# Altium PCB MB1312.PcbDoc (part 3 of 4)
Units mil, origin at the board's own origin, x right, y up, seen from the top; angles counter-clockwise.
Board outline 2755.91 x 5249.6 mil, 6 copper layers (Top Layer, GND, Signal, PWR, GND (Mid2), Bottom Layer), stack 74.545 mil thick; 297 components, 280 nets, 1142 pads, 623 vias.
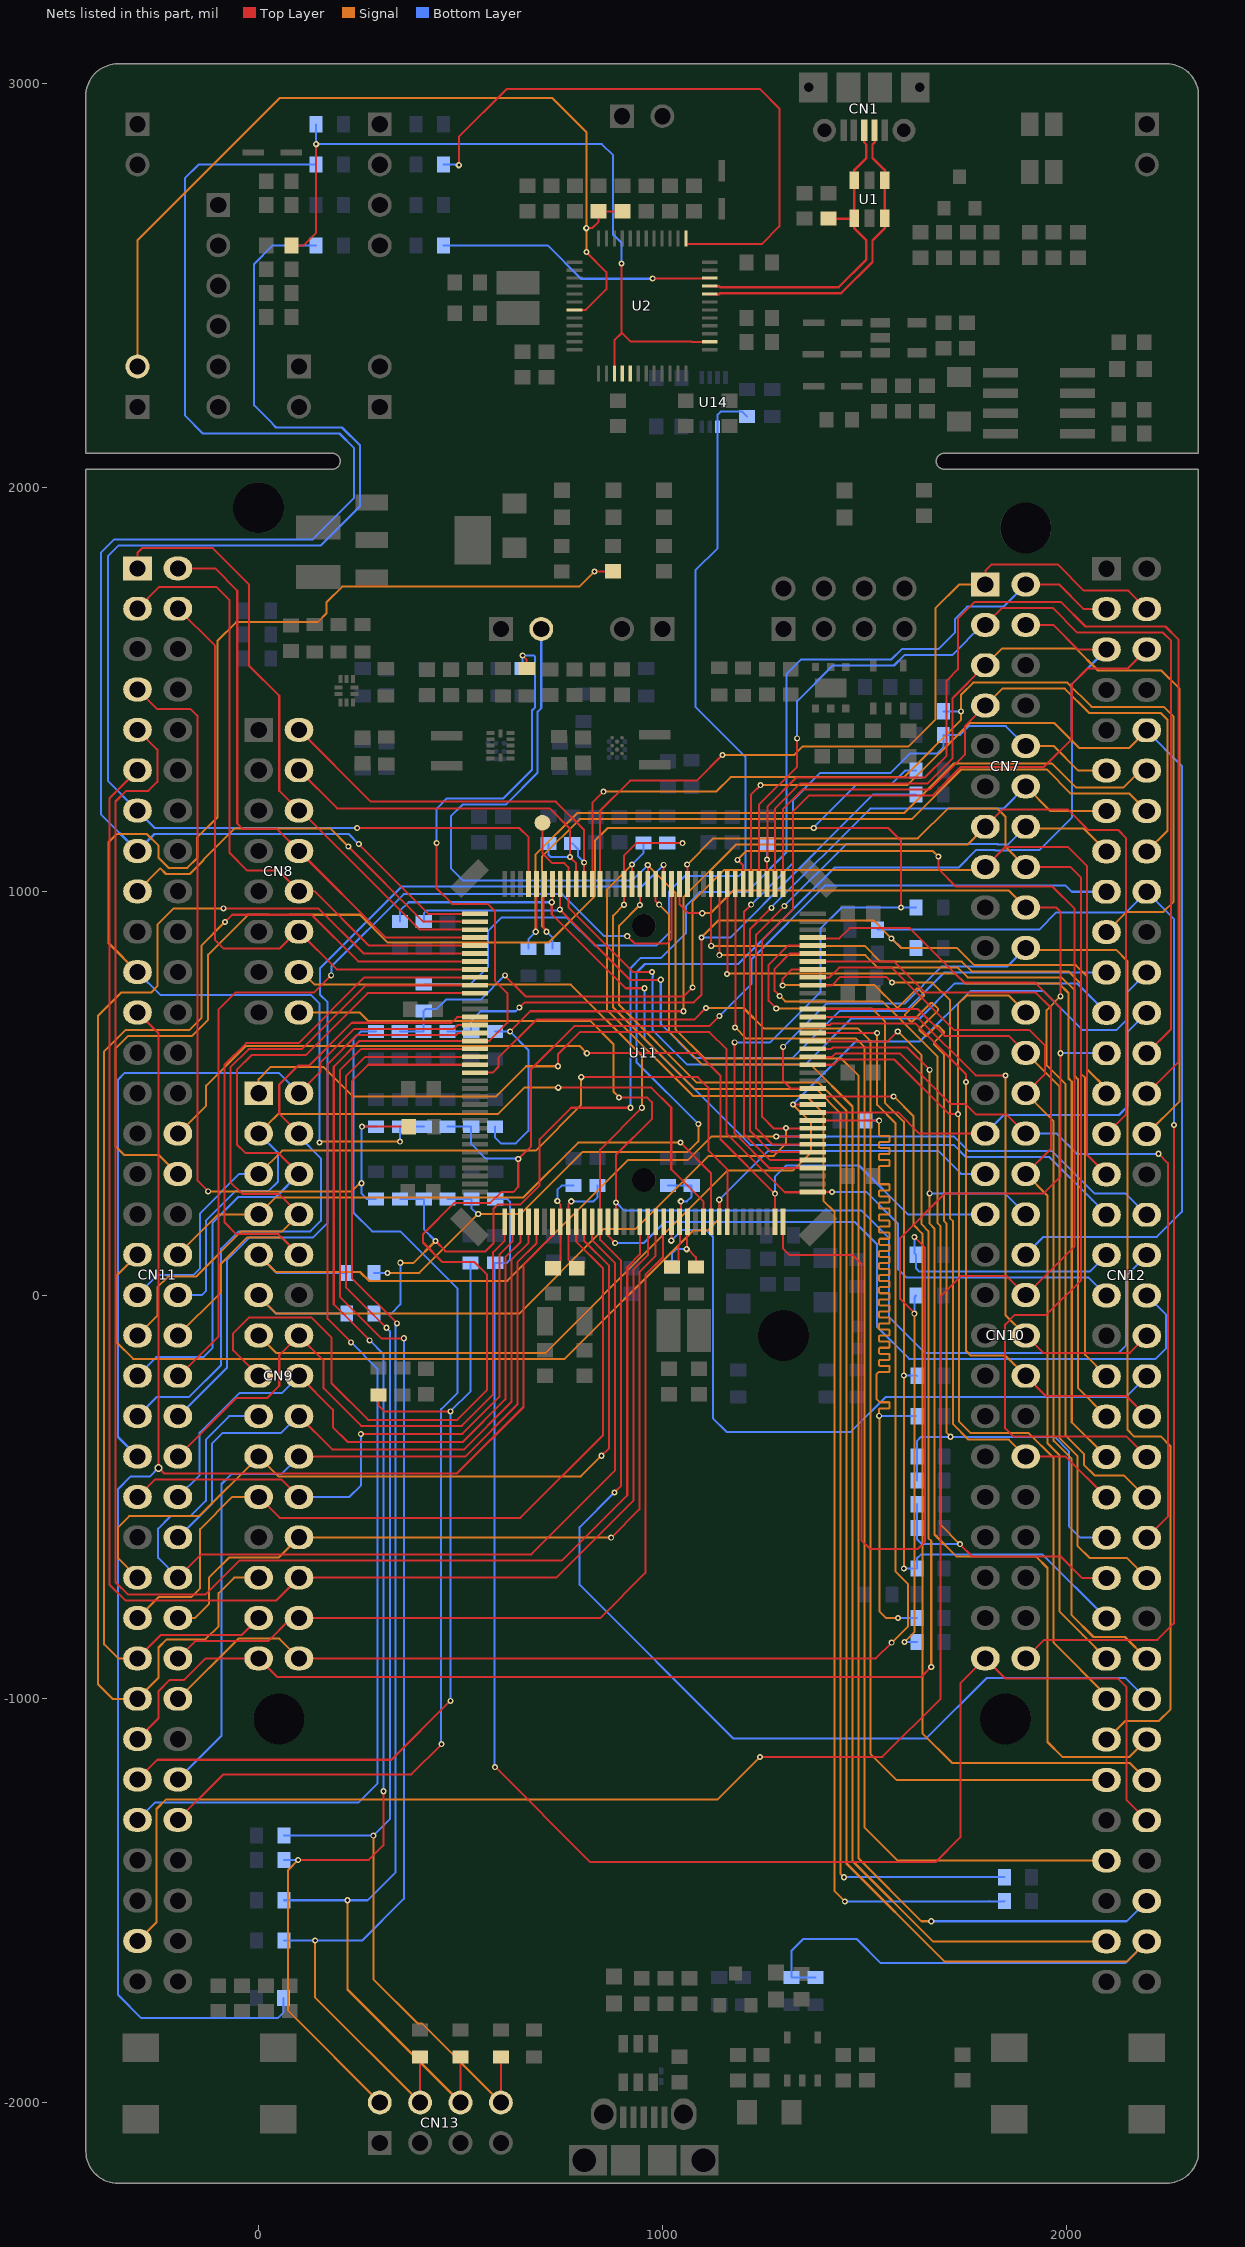
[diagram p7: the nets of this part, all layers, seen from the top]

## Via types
v1: diameter 15, hole 8, Top Layer to Bottom Layer, tented both sides, 405 vias
v2: diameter 16, hole 8, Top Layer to Bottom Layer, tented both sides, 179 vias
v3: diameter 20, hole 12, Top Layer to Bottom Layer, tented both sides, 39 vias

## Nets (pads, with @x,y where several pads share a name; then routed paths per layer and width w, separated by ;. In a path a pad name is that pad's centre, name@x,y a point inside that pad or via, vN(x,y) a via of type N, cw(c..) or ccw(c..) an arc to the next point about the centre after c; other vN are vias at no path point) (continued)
PA1: CN10.11 CN11.30 U11.35 | length 2548.5
  Top Layer w5: v2@813.19,600 1087,600 1144,543 1144,386 1278.71,251.3 v1(1278.71,251.1) ; 1270,259.61 v1@1278.51,251.1 ; U11.35@1278.8,181.69 1278.8,251.2 v1(1278.71,251.1) ; v1@1278.51,251.1 v1(1278.71,251.1) ; v1@1278.51,251.1 1278.61,251 v1(1278.71,251.1)
  Signal w5: CN11.30@-200,400 -199.04,400 -130,469.04 -130,518.57 -31.62,616.95 -25.15,616.95 795.24,616.95 v2(813.19,599)
  Bottom Layer w5: v1(1278.71,251.1) 1278.71,292.71 1307,321 1487,321 1608,200 CN10.11@1800,200
PA2: CN12.35 SB150.1 U11.36 | length 2473.3
  Top Layer w5: U11.36@1298.49,181.69 1298.49,115.92 1315.41,99 1472,99 1493,78 1493,-607 1515,-629 1633,-629 1651,-611 1651,117 v1(1624,144)
  Bottom Layer w5: v1(1624,144) 1624,104.25 SB150.1@1628.25,100 1628.25,66.75 1628.51,66.49 ; 1628.25,66.22 1636.5,57.97 2058.97,57.97 CN12.35@2100,99
PA3: CN9.1 CN12.37 U11.37 | length 2725.3
  Top Layer w5: v1(741.5,566.79) 741.5,597.03 795.85,651.38 1116.62,651.38 1159,609 1159,399.28 1303.59,254.7 1371.49,254.7 U11.37@1372.31,255.51 v1(1419.99,255.51) v1@1421,254.5
  Signal w5: CN9.1@0,500 0,535 30.47,565.47 160.53,565.47 234.27,491.73 587.73,491.73 662.79,566.79 v1(741.5,566.79) ; v1@743.25,565.04 v1@745,566.79
  Bottom Layer w5: v1(1419.99,255.51) 1504.49,255.51 1584,176 1584,63.97 1605,42.97 2056.03,42.97 CN12.37@2100,-1
PA4: CN11.32 SB126.1 SB133.1 U11.40 | length 4453.9
  Top Layer w5: v1(1179,626) 1179,400.5 1264.8,314.7 1372.18,314.7 U11.40@1372.31,314.57 ; v1(1375,1157) 1559,1157 1591,1125 v1(1591,960)
  Signal w5: CN11.32@-200,300 -247,347 -332.94,347 -354,368.06 -354,611.34 -323.31,642.03 -164.76,642.03 -125,681.79 -125,843 -25.97,942.03 23.31,942.03 ; 23.34,942 76.66,942 ; 76.69,942.03 250.97,942.03 320,873 717.87,873 833,988.13 833,1125.53 864.47,1157 v1(1375,1157)
  Bottom Layer w5: v1(1179,626) 1267,626 1391.25,750.25 1391.25,907.25 1444,960 v1(1591,960) SB133.1@1628.25,960 ; v1(1375,1157) 1375,1158.76 1480.24,1264 1566,1264 1601,1299 SB126.1@1628.25,1299
PA5: CN7.10 CN12.11 SB123.2 U11.41 | length 1989.7
  Top Layer w5: v1(1220,967) 1202.1,949.1 1202.1,398.86 1266.71,334.25 U11.41@1372.31,334.25
  Signal w5: CN7.10@1900,1360 1969,1360 2030,1299 CN12.11@2100,1299
  Bottom Layer w5: v1(1220,967) 1323,1070 1323,1225 1391.5,1293.5 1565.5,1293.5 1613,1341 1680,1341 1695.75,1356.75 SB123.2@1695.75,1387 1737,1387 1759,1409 1851,1409 CN7.10@1900,1360
PA6: CN7.12 CN12.13 U11.42 | length 1731.9
  Top Layer w5: v1(1270.13,959.13) 1217.1,906.1 1217.1,406.9 1270.06,353.94 U11.42@1372.31,353.94
  Signal w5: CN7.12@1900,1260 1961,1199 CN12.13@2100,1199
  Bottom Layer w5: v1(1270.13,959.13) 1270.13,960.42 1514.72,1205 1845,1205 CN7.12@1900,1260
PA7: CN7.14 CN12.15 U11.43 | length 1646.6
  Top Layer w5: v1(1302,964) 1303.28,964 1232.1,892.82 1232.1,413.11 1272.21,373 1372.31,373 U11.43@1372.31,373.62
  Signal w5: CN7.14@1900,1160 1900,1155.6 2043.4,1155.6 CN12.15@2100,1099
  Bottom Layer w5: v1(1302,964) 1455.03,1117.03 1829.53,1117.03 1830.05,1116.51 1856.51,1116.51 CN7.14@1900,1160
PA8: CN12.23 TP1.1 U11.100 | length 1944.9
  Top Layer w5: TP1.1@703,1170 703,1094 727,1070 757,1070 766.99,1060.01 U11.100@766.99,1018.31 766.99,961.01 928,800 v1(974,800)
  Bottom Layer w5: v1(974,800) 976.9,797.1 976.9,790.18 976,789.28 976,656.26 1061.26,571 1354,571 1468,685 1637.31,685 1724.31,772 2027,772 CN12.23@2100,699
PA9: CN12.21 SB135.2 U11.101 | length 2085.1
  Top Layer w5: U11.101@747.31,1018.31 746,1017 v1(746,955) 921,780 995,780 v1(996,781) v1@995,782
  Bottom Layer w5: SB135.2@409,925.75 409,946 416,953 744,953 v1(746,955) ; v1(996,781) 996,672 1080.9,587.1 1322.1,587.1 1439,704 1603.21,704 1698.21,799 CN12.21@2100,799
PA10: CN12.33 SB134.2 U11.102 | length 2244.8
  Top Layer w5: U11.102@727.62,1018.31 727.62,973.62 727,973 v1(726,973) 726,942.79 908.79,760 v1(956,760)
  Bottom Layer w5: SB134.2@350,925.75 350,951.57 371.43,973 v1(726,973) ; v1(956,760) 956,633.5 1217.4,372.1 1721.83,372.1 1751.9,342.03 1958.76,342.03 2064.79,236 2065,236 2100,201 CN12.33@2100,199
PA11: CN12.14 SB142.2 U11.103 | length 1991
  Top Layer w5: U11.103@707.94,1018.31 706,1016.37 706,909.27 713,902.27 v2(713,900)
  Signal w5: v2(713,900) 713,902.27 701.28,913.99 701.28,1085.26 795.03,1179 1617.97,1179 1741,1302.03 1951.97,1302.03 2012.03,1241.97 2157.03,1241.97 CN12.14@2200,1199
  Bottom Layer w5: v2(713,900) 728,885 SB142.2@728,858.5
PA12: CN12.12 SB143.2 U11.104 | length 2008.9
  Top Layer w5: v2(686.28,900) 688.25,901.97 U11.104@688.25,1018.31
  Signal w5: v2(686.28,900) 686.28,1091.47 788.81,1194 1599.34,1194 1722.37,1317.03 1964.97,1317.03 2025.03,1256.97 2142.03,1256.97 2184.06,1299 CN12.12@2200,1299
  Bottom Layer w5: SB143.2@668.57,858.5 668.57,882.28 v2(686.28,900)
PA13: CN11.13 SB106.1 U11.105 | length 3423.8
  Top Layer w5: v1(244,1157) 646,1157 668.57,1134.43 U11.105@668.57,1018.31
  Bottom Layer w5: -229.55,1157 -257,1157 CN11.13@-300,1200 -373,1273 -373,1830.85 -346.82,1857.03 154.47,1857.03 251,1953.56 251,2104.46 206.46,2149 42.9,2149 34,2157.9 ; -229.53,1157.03 -170.47,1157.03 ; -170.45,1157 -29.55,1157 ; -29.53,1157.03 29.53,1157.03 ; 29.55,1157 70.45,1157 ; 34,2159 -11,2204 -11,2554 35,2600 SB106.1@142.25,2600 ; 70.47,1157.03 129.53,1157.03 ; 129.55,1157 v1(244,1157)
PA14: CN11.15 SB102.1 U11.109 | length 3897.3
  Top Layer w5: v1(248.03,1117) 420.54,944.49 U11.109@535.69,944.49
  Bottom Layer w5: -223.34,1142 -258,1142 CN11.15@-300,1100 -390.9,1190.9 -390.9,1838.76 -357.63,1872.03 134.03,1872.03 236,1974 236,2098.25 200.25,2134 -138,2134 -183,2179 -183,2766 -149,2800 SB102.1@142.25,2800 ; -223.31,1142.03 -176.69,1142.03 ; -176.66,1142 -23.34,1142 ; -23.31,1142.03 23.31,1142.03 ; 23.34,1142 76.66,1142 ; 76.69,1142.03 123.31,1142.03 ; 123.34,1142 223.03,1142 v1(248.03,1117)
PA15: CN11.17 U11.110 | length 1008.4
  Top Layer w5: v1(222,1111) 408.2,924.8 U11.110@535.69,924.8
  Signal w5: CN11.17@-300,1000 -243.28,1056.72 -229.53,1042.97 -170.47,1042.97 -137.07,1076.38 -137.07,1077.93 -59,1156 177,1156 v1(222,1111)
PB0: SB144.2 SB159.1 SB182.1 U11.46 | length 2583.2
  Top Layer w5: U11.46@1372.31,432.68 1536.32,432.68 v1(1537,432)
  Signal w5: v1(1537,-299) 1537,-282 1538.5,-280.5 1561.5,-280.5 1563,-279 1563,-267 1561.5,-265.5 1538.5,-265.5 1530,-257 1530,-196 1535.5,-190.5 1561.5,-190.5 1563,-189 1563,-177 1561.5,-175.5 1538.5,-175.5 1537,-174 1537,-162 1538.5,-160.5 1561.5,-160.5 1563,-159 1563,-147 1561.5,-145.5 1538.5,-145.5 1537,-144 1537,-132 1538.5,-130.5 1561.5,-130.5 1563,-129 1563,-117 1561.5,-115.5 1538.5,-115.5 1537,-114 1537,-102 1538.5,-100.5 1561.5,-100.5 1563,-99 1563,-87 1561.5,-85.5 1538.5,-85.5 1537,-84 1537,-72 1538.5,-70.5 1561.5,-70.5 1563,-69 1563,-57 1561.5,-55.5 1538.5,-55.5 1537,-54 1537,-42 1538.5,-40.5 1561.5,-40.5 1563,-39 1563,-27 1561.5,-25.5 1538.5,-25.5 1537,-24 1537,-12 1538.5,-10.5 1561.5,-10.5 1563,-9 1563,3 1561.5,4.5 1538.5,4.5 1537,6 1537,18 1538.5,19.5 1561.5,19.5 1563,21 1563,33 1561.5,34.5 1538.5,34.5 1537,36 1537,48 1538.5,49.5 1561.5,49.5 1563,51 1563,63 1561.5,64.5 1538.5,64.5 1537,66 1537,78 1538.5,79.5 1561.5,79.5 1563,81 1563,93 1561.5,94.5 1538.5,94.5 1537,96 1537,108 1538.5,109.5 1561.5,109.5 1563,111 1563,123 1561.5,124.5 1538.5,124.5 1537,126 1537,138 1538.5,139.5 1561.5,139.5 1563,141 1563,153 1561.5,154.5 1538.5,154.5 1537,156 1537,168 1538.5,169.5 1561.5,169.5 1563,171 1563,183 1561.5,184.5 1538.5,184.5 1537,186 1537,198 1538.5,199.5 1561.5,199.5 1563,201 1563,213 1561.5,214.5 1538.5,214.5 1537,216 1537,228 1538.5,229.5 1561.5,229.5 1563,231 1563,243 1561.5,244.5 1538.5,244.5 1537,246 1537,258 1538.5,259.5 1561.5,259.5 1563,261 1563,273 1561.5,274.5 1538.5,274.5 1537,276 1537,318 1538.5,319.5 1561.5,319.5 1563,321 1563,333 1561.5,334.5 1538.5,334.5 1537,336 1537,348 1538.5,349.5 1561.5,349.5 1563,351 1563,363 1561.5,364.5 1538.5,364.5 1537,366 1537,378 1538.5,379.5 1561.5,379.5 1563,381 1563,393 1561.5,394.5 1538.5,394.5 1537,396 v1(1537,432) ; v1@1538,-299 1538,-784 1554.21,-800.21 v1(1583.79,-800.21)
  Bottom Layer w5: SB144.2@1504.75,433 1505.75,432 v1(1537,432) ; v1(1537,-299) 1623.25,-299 1625.25,-297 SB159.1@1628.25,-300 ; v1@1583.79,-800 SB182.1@1630.25,-800
PB1: CN10.7 CN12.24 U11.47 | length 1081
  Top Layer w5: U11.47@1372.31,452.36 1584.29,452.36 1636.66,400 CN10.7@1800,400
  Bottom Layer w5: CN10.7@1800,400 1846,446 2131,446 2152,467 2152,651 CN12.24@2200,699
PB2: CN9.13 CN12.22 U11.48 | length 2910.1
  Top Layer w5: v1(1323.31,472.05) U11.48@1372.31,472.05
  Signal w5: CN9.13@0,-100 43,-143 70.45,-143 ; 70.47,-142.97 129.53,-142.97 ; 129.55,-143 711.28,-143 850,-4.28 850,-3 1162,309 1324,309 1368.36,353.36 1368.36,426.99 v1(1323.31,472.05)
  Bottom Layer w5: v1(1323.31,472.05) 1479.26,628 1638,628 1763.38,753.38 1943.26,753.38 2039.67,656.97 2124.97,656.97 2150,682 2150,749 CN12.22@2200,799
PB3: CN7.15 CN12.31 SB141.2 SB161.2 SB162.2 | length 2877.4
  Top Layer w5: v1(610,792) 610,791 661,740 1053,740 v1(1075,762) ; CN7.15@1800,1060 1850,1110 2004,1110 2052.07,1061.93 2052.07,346.93 CN12.31@2088,311
  Signal w5: v1(1075,762) 1075,975 1153,1053 1793,1053 CN7.15@1800,1060
  Bottom Layer w5: SB161.2@349.53,652.5 SB162.2@408.53,652.48 408.53,703.25 413.28,708 440,708 464,732 550,732 v1(610,792) v1@609,793
PB4: CN12.27 SB128.1 SB140.1 SB163.2 SB164.2 | length 2916.1
  Top Layer w5: v1(645.6,712) 658.6,725 1077.87,725 1097,744.13 v1(1097,886)
  Signal w5: v1(1097,886) 1139,928 1523,928 1567,884 v1(1567,883) 1568,883 1591,860 1729,860 1772,817 2024,817 2051.8,789.2 2051.8,559.81 2100,511.61 CN12.27@2100,499
  Bottom Layer w5: SB164.2@467.53,652.75 SB163.2@526.53,652.75 526.53,679.42 550.11,703 636.6,703 v1(645.6,712) ; v1(1097,886) 1169,886 1250.13,967.13 1250.13,967.42 1522.72,1240 SB128.1@1628.25,1240 ; v1(1567,883) 1568,883 1591,860 SB140.1@1628.25,860 ; CN12.27@2100,499 CN12.27@2100,501
PB5: CN7.13 CN12.29 SB165.2 SB176.2 | length 3133
  Top Layer w5: v1(623,653) 623,653.5 672.5,703 v1(1052,703) ; CN7.13@1800,1160 1842.95,1202.95 1986.15,1202.95 2004.05,1202.95 2055,1152 2129,1152 2148.97,1132.03 2148.97,447.97 CN12.29@2100,399
  Signal w5: v1(1052,703) 1052,984.91 1183.09,1116 1756,1116 CN7.13@1800,1160
  Bottom Layer w5: SB176.2@585.3,418 585.3,390.7 600,376 637,376 668,407 668,607 623,652 v1(623,653) 585.78,653 SB165.2@585.53,652.75
PB6: CN9.15 CN12.17 SB174.2 SB175.2 | length 3959.7
  Top Layer w5: CN9.15@0,-200 -63,-137 -63,-95 -23,-55 130,-55 181,-106 181,-219 271,-309 492,-309 566,-235 566,49.82 533.82,82 455.17,82 407,130.17 407,151 484.15,228.15 574.09,228.15 601.14,255.2 630.3,255.2 643,267.89 v1(643,337) 675,369 675,559.98 781.4,666.38 1116.38,666.38 v1(1141,691)
  Signal w5: CN12.17@2096.97,1002.03 CN12.17@2100,999
  Bottom Layer w5: SB174.2@468,417 526.03,417 526.53,417.5 526.53,374.47 563,338 642,338 v1(643,337) ; v1(1141,691) 1221,771 1221,832.34 1402.66,1014 1999.1,1014 2014.1,999 CN12.17@2100,999
PB7: CN11.21 R30.1 SB172.2 SB173.2 | length 3392.2
  Top Layer w5: v1@832.03,1792.5 R30.1@878,1792.5
  Signal w5: CN11.21@-300,800 -372,872 -372,1122 -351.97,1142.03 -276.69,1142.03 -247.93,1113.27 -247.93,1082.59 -223.31,1057.97 -176.69,1057.97 -152.07,1082.59 -152.07,1133.93 -102,1184 -102,1621 -56,1667 146,1667 168,1689 168,1716 206.74,1754.74 794.26,1754.74 v1(832,1792.47) ; v1(151,378) 154,378 156,380 v1(350,380)
  Bottom Layer w5: CN11.21@-300,800 -242.97,742.97 130.03,742.97 151,722 v1(151,378) ; v1(350,380) SB172.2@350,417 SB173.2@409,417
PB8: CN7.2 CN12.3 SB153.2 SB181.2 SB184.2 | length 3487.5
  Top Layer w5: v1(438,134) 463.86,108.14 ; 462.14,108.14 463.86,108.14 ; v1(921,464) 774,464 696,386 696,271.89 648.79,224.67 592.39,224.67 581.72,214 581.72,128 561.86,108.14 463.86,108.14 ; CN7.2@1900,1760 1983,1760 2044,1699 CN12.3@2100,1699
  Signal w5: v1(351,80) 384,80 v1(438,134)
  Bottom Layer w5: SB153.2@285,-45.25 SB153.2@285.75,-46 328,-46 351,-23 v1(351,80) ; SB184.2@350,238 SB181.2@409,238 409,163 v1(438,134) ; v1@921.37,461 921,461.37 v1(921,464) 921,810 946,835 997,835 1058,896 1058,963.53 1092.47,998 1209,998 1307.2,1096.2 1307.2,1537.26 1344.44,1574.5 1567.49,1574.5 1592.99,1600 1683,1600 1725,1642 1725,1675 1755,1705 1845,1705 CN7.2@1900,1760
PB9: CN7.4 CN12.5 SB151.2 SB185.2 SB186.2 | length 3440.2
  Top Layer w5: CN7.4@1900,1660 1968,1660 2029,1599 CN12.5@2100,1599
  Signal w5: v1(319,55) 398,55 v1(544,201) 648.72,201 801.72,354 1062.06,354 1089,380.94 v1(1089,424)
  Bottom Layer w5: SB151.2@285.75,55 v1(319,55) ; SB186.2@468,238 SB185.2@527,238 527,215.22 541.22,201 v1(544,201) ; v1(1089,424) 936,577 936,799 957,820 1187.44,820 1426.44,1059 1733.66,1059 1776.69,1102.03 1823.31,1102.03 1823.84,1101.51 1862.72,1101.51 1863.82,1102.61 1934.61,1102.61 2015.1,1183.1 2015.1,1394.41 2014,1395.51 2014,1513 CN12.5@2100,1599
PB10: CN12.25 SB155.1 SB188.2 U11.69 | length 2802.2
  Top Layer w5: U11.69@1372.31,885.43 1374.24,883.5 1438.5,883.5 1464,909 1613,909 1748,774 1923.72,774 1986,711.72 v1(1986,599) 1986,293 1945,252 1700,252 1589,141 1589,-9.34 v1@1624.83,-45.17
  Signal w5: v1(1599.9,-859) 1624,-834.9 v1(1624,-46)
  Bottom Layer w5: v1(1599.9,-859) SB188.2@1630.25,-859 ; v1(1624,-46) 1624,-9.25 1626,-7.25 1624,-5.25 SB155.1@1628.25,-1 ; v1(1986,599) CN12.25@2100,599
PB11: CN10.34 CN12.18 SB138.2 | length 2949
  Top Layer w5: CN10.34@1900,-900 1946,-854 2226.03,-854 2267,-813.03 v1(2267,421)
  Bottom Layer w5: SB138.2@1532.75,905 1933,905 1976,948 2149,948 CN12.18@2200,999 2267,932 v1(2267,421)
PB12: CN7.7 CN12.16 U11.73 | length 1681.6
  Top Layer w5: U11.73@1298.49,1018.31 1298.5,1203.5 1347,1252 1662.31,1252 1750,1339.69 1750,1410 CN7.7@1800,1460
  Signal w5: CN7.7@1800,1460 1842.03,1502.03 1996.76,1502.03 2056.81,1441.97 2233.81,1441.97 2251.2,1424.59 2251.2,1150.2 CN12.16@2200,1099
PB13: CN7.5 CN12.30 U11.74 | length 2632.3
  Top Layer w5: U11.74@1278.8,1018.31 1279.12,1018.62 1279.12,1205.33 1340.79,1267 1656.1,1267 1719,1329.9 1719,1479 CN7.5@1800,1560 ; CN12.30@2200,399 CN12.30@2206.74,399
  Signal w5: CN7.5@1800,1560 1842.03,1602.03 1923.31,1602.03 ; 1923.34,1602 2024,1602 2079,1547 2236,1547 2281.2,1501.8 2281.2,480.2 CN12.30@2200,399
  Bottom Layer w5: CN12.30@2200,399 CN12.30@2206.74,399
PB14: CN12.28 SB132.1 U11.75 | length 2849.7
  Top Layer w5: U11.75@1259.12,1018.31 v1(1259.12,1079.19) ; v1@1259.93,1079.19 1259.93,1209.93 1332,1282 1649.89,1282 1704,1336.11 1704,1521.75 1732,1549.75 1732,1675 1774.03,1717.03 1986.97,1717.03 2048,1656 2070.45,1656 ; 2070.47,1656.03 2246.19,1656.03 2278,1624.21 2278,577 CN12.28@2200,499
  Bottom Layer w5: v1(1259.12,1079.19) 1259.12,1117.12 SB132.1@1261,1119 SB132.1@1261,1130.25
PB15: CN7.3 CN12.26 U11.76 | length 2596.3
  Top Layer w5: U11.76@1239.43,1018.31 1239.12,1018.62 1239.12,1214.12 1334,1309 v1(1334,1379) v1@1334,1381 ; CN7.3@1800,1660 1842.03,1702.03 1966.87,1702.03 2027.9,1641 2076.66,1641 ; 2076.69,1641.03 2239.97,1641.03 2260,1621 2260,659 CN12.26@2200,599
  Bottom Layer w5: v1(1334,1379) 1334,1471 1422.5,1559.5 1573.7,1559.5 1599.2,1585 1717.79,1585 1792.79,1660 CN7.3@1800,1660
PC0: CN9.3 CN11.38 U11.26 | length 1976.5
  Top Layer w5: v2(742,514) 972.6,514 1022,464.6 1022,311.5 1101.64,231.86 U11.26@1101.64,181.69
  Signal w5: 24.17,424.17 48,448 592,448 658,514 v2(742,514)
  Bottom Layer w5: CN11.38@-200,0 -141,0 -130,11 -130,185 -57.03,257.97 24.97,257.97 47.93,280.93 47.93,352.07 CN9.3@0,400
PC1: CN9.7 CN11.36 U11.27 | length 1587.5
  Top Layer w5: v1(1045,377.59) 1120.5,302.09 1120.5,182.52 U11.27@1121.32,181.69
  Signal w5: CN11.36@-200,100 -100,200 CN9.7@0,200 41.9,241.9 76.56,241.9 76.69,242.03 656.03,242.03 791.59,377.59 v1(1045,377.59)
PC2: CN10.9 CN11.35 U11.28 | length 2734.8
  Top Layer w5: U11.28@1141,181.7 v2(1141,236)
  Signal w5: CN11.35@-300,100 -352.8,47.2 -352.8,-116.2 -311.03,-157.97 -276.69,-157.97 ; -276.66,-158 -223.34,-158 ; -223.31,-157.97 -176.69,-157.97 ; -176.66,-158 -23.34,-158 ; -23.31,-157.97 23.31,-157.97 ; 23.34,-158 76.66,-158 ; 76.69,-157.97 123.31,-157.97 ; 123.34,-158 757.99,-158 1076,160 1112,160 1141,189 v2(1141,236)
  Bottom Layer w5: v2(1141,236) 1262.1,357.1 1682.9,357.1 1740,300 CN10.9@1800,300 CN10.9@1807.72,300
PC3: CN9.5 CN11.37 U11.29 | length 2120.5
  Top Layer w5: v2(799,540) 1088,540 1114,514 1114,358.79 1142.39,330.39 ; 1142,330 1161.51,310.49 1161.51,230 ; U11.29@1160.69,181.69 1161.5,182.5 1161.5,229.99
  Signal w5: CN9.5@0,300 57.97,357.97 685.97,357.97 799,471 v2(799,540)
  Bottom Layer w5: CN11.37@-300,0 -250.75,49.25 -162.5,49.25 -145,66.75 -145,202.56 -47.56,300 CN9.5@0,300
PC4: CN9.9 CN12.34 SB151.1 U11.44 | length 2783.1
  Top Layer w5: v1(1282,393) 1282.31,393.31 U11.44@1372.31,393.31
  Signal w5: CN9.9@0,100 42.88,57.12 251.12,57.12 273.25,35 616,35 915.73,334.73 1064,334.73 1122.27,393 v1(1282,393)
  Bottom Layer w5: CN9.9@0,100 45.25,54.75 218,54.75 SB151.1@218.25,55 ; v1(1282,393) 1722.14,393 1758.11,357.03 1964.97,357.03 2071,251 2148,251 CN12.34@2200,199
PC5: CN9.11 CN12.6 SB153.1 U11.45 | length 3825.2
  Top Layer w5: v1@1304.82,412.18 1276.52,412.18 1247.1,441.6 1247.1,879.66 1323,955.56 1323,1197 1363,1237 1668.53,1237 1739.5,1307.97 1944.97,1307.97 2014,1377 2014,1513 2053,1552 2153,1552 CN12.6@2200,1599 ; v1@1306.02,412.18 1372.31,412.18 U11.45@1372.31,412.99
  Signal w5: CN9.11@0,0 0,-2.23 43.77,-46 645,-46 855,164 934,164 1115,345 1276,345 1306.02,375.02 v1(1306.02,413.78)
  Bottom Layer w5: CN9.11@0,0 0,-2.23 43.77,-46 SB153.1@218.25,-46
PC6: CN7.1 CN12.4 U11.96 | length 2016.7
  Top Layer w5: U11.96@845.73,1018.31 845,1019.04 845,1199 920,1274 1085,1274 v1(1149,1338) ; CN7.1@1800,1760 1800,1794 1816,1810 1979,1810 2044,1745 2154,1745 CN12.4@2200,1699
  Signal w5: v1(1149,1338) 1327,1338 1348,1359 1610,1359 1677,1426 1677,1702 1735,1760 CN7.1@1800,1760
PC7: CN12.19 SB124.1 U11.97 | length 2535.6
  Top Layer w5: U11.97@826.05,1018.31 826.36,1018.62 826.36,1219.16 v1(853.99,1246.79)
  Signal w5: v1(853.99,1246.79) 1132.79,1246.79 1169,1283 1598.43,1283 1740,1424.57 v1(1740,1446) 1740,1487.5 1769.53,1517.03 2002.97,1517.03 2063.03,1456.97 2241.58,1456.97 2266.2,1432.36 2266.2,974.2 2241,949 2150,949 CN12.19@2100,899
  Bottom Layer w5: SB124.1@1696,1446 v1(1740,1446)
PC8: CN8.2 SB137.1 U11.98 | length 1002.6
  Top Layer w5: CN8.2@100,1400 278,1222 736.3,1222 806.36,1151.94 v1(806.36,1071.42) U11.98@806.36,1018.31
  Bottom Layer w5: SB137.1@776.7,1119 791,1104.7 791,1086.78 v1(806.36,1071.42)
PC9: CN8.4 SB136.1 U11.99 | length 986.4
  Top Layer w5: CN8.4@100,1300 194.67,1205.33 721.31,1205.33 771,1155.64 v1(771,1085) ; v1@775,1081 786.36,1069.64 786.36,1052.31 786.68,1052 U11.99@786.68,1018.31 786.36,1018.62 786.36,1052
  Bottom Layer w5: SB136.1@717.7,1119 717.7,1091.3 724,1085 v1(771,1085)
PC10: CN8.6 CN11.1 U11.111 | length 1526.3
  Top Layer w5: CN11.1@-300,1800 -300,1839 -289,1850 -113.49,1850 -24,1760.51 -24,1559.5 51,1484.5 51,1249 CN8.6@100,1200 103.99,1200 398.87,905.12 U11.111@535.69,905.12
PC11: CN8.8 CN11.2 U11.112 | length 1452.5
  Top Layer w5: CN11.2@-200,1800 -108,1800 -53,1745 -53,1168 -39,1154 46,1154 CN8.8@100,1100 314.57,885.43 U11.112@535.69,885.43
PC12: CN8.10 CN11.3 U11.113 | length 1592.7
  Top Layer w5: CN11.3@-300,1700 -246,1754 -105,1754 -72,1721 -72,1095 -29,1052 48,1052 CN8.10@100,1000 139,1000 273.25,865.75 U11.113@535.69,865.75
PC13: CN11.23 SB197.1 U11.7 | length 4466.9
  Top Layer w5: CN11.23@-300,700 -248,648 v3(-248,-428) -234,-442 -223.34,-442 ; -223.31,-442.03 -176.69,-442.03 ; -176.66,-442 -23.34,-442 ; -23.31,-442.03 23.31,-442.03 ; 23.34,-442 63.21,-442 ; 63.24,-442.03 491.18,-442.03 656,-277.21 656,75 727.62,146.62 U11.7@727.62,181.69
  Bottom Layer w5: v3(-248,-428) -269,-449 -317,-449 -348.46,-480.46 -348.46,-1733.54 -291,-1791 47,-1791 61.75,-1776.25 SB197.1@61.75,-1741
PC14: R39.2 SB145.1 U11.8 | length 248.7
  Top Layer w5: R39.2@729,66.75 748.12,85.87 748.12,180.88 U11.8@747.31,181.69 747.31,224.63 v2@740,231.94
  Bottom Layer w5: v2(740,233) 740,261 750.25,271.25 SB145.1@780,271.25
PC15: R40.2 SB146.1 U11.9 | length 275.6
  Top Layer w5: v2(774.3,231.94) 766.99,224.63 U11.9@766.99,181.69 766.99,87.5 R40.2@788,66.5
  Bottom Layer w5: v2(774.3,231.94) 829.44,231.94 839,241.5 SB146.1@839,271.25
PD0: CN9.25 CN11.57 U11.114 | length 3464.1
  Top Layer w5: v1(-86.94,957.97) 148.03,957.97 259.94,846.06 U11.114@535.69,846.06
  Signal w5: v1(-86.94,957.97) -209.96,957.97 -251,916.93 -251,765 -266.5,749.5 -340.3,749.5 -397.95,691.85 -397.95,-964.05 -362,-1000 CN11.57@-300,-1000 -248,-948 -248,-873 -228,-853 -132,-853 -99,-820 -99,-738.21 -60.79,-700 CN9.25@0,-700
PD1: CN9.27 CN11.55 U11.115 | length 3119.9
  Top Layer w5: CN11.55@-300,-900 -242.03,-842.03 -42.03,-842.03 CN9.27@0,-800 ; v1@-84,924 v1(-83.46,924) -65.44,942.03 130.97,942.03 246.62,826.38 U11.115@535.69,826.38
  Signal w5: CN11.55@-300,-900 -348.03,-900 -382.95,-865.07 -382.95,603.6 -329.53,657.03 -170.97,657.03 -141,687 -141,866.46 v1(-83.46,924)
PD2: CN8.12 CN11.4 U11.116 | length 1567.6
  Top Layer w5: CN11.4@-200,1700 -108,1608 -108,879 -86.97,857.97 51.59,857.97 93.62,900 CN8.12@100,900 193.31,806.69 U11.116@535.69,806.69
PD3: CN9.10 CN11.40 U11.117 | length 1778.4
  Top Layer w5: CN9.10@100,100 49,151 -54.97,151 -85,181.03 -85,570.46 -31.24,624.22 99.13,624.22 261.92,787.01 U11.117@535.69,787.01
  Signal w5: CN11.40@-200,-100 -94,6 -94,77 -28.03,142.97 57.03,142.97 CN9.10@100,100
PD4: CN9.8 CN11.39 U11.118 | length 1742.5
  Top Layer w5: CN9.8@100,200 49.5,250.5 -40.55,250.5 -70,279.95 -70,564.24 -25.03,609.22 107.22,609.22 265.32,767.32 U11.118@535.69,767.32
  Signal w5: CN11.39@-300,-100 -251,-51 -251,19 -224,46 -155,46 -43.03,157.97 57.97,157.97 CN9.8@100,200
PD5: CN9.6 CN11.41 U11.119 | length 1826.6
  Top Layer w5: CN9.6@100,300 48,352 -33,352 -54,373 -54,558 -17.78,594.22 116.71,594.22 270.13,747.64 U11.119@535.69,747.64
  Bottom Layer w5: CN11.41@-300,-200 -254,-154 -137,-154 -114,-131 -114,179.79 -50.81,242.97 42.97,242.97 CN9.6@100,300
PD6: CN9.4 CN11.43 U11.122 | length 1757.7
  Top Layer w5: CN9.4@100,400 51,449 51,521.63 98,568.63 125.2,568.63 231.1,674.53 477.52,674.53 491.57,688.58 U11.122@535.69,688.58
  Bottom Layer w5: CN11.43@-300,-300 -253,-253 -172.66,-253 -92.9,-173.24 -92.9,114.76 -49.68,157.97 128.32,157.97 154.19,183.85 154.19,338.81 100,393 CN9.4@100,400
PD7: CN9.2 CN11.45 U11.123 | length 1947.8
  Top Layer w5: CN9.2@100,500 153,553 153,575.21 237.31,659.53 483.73,659.53 493.1,668.9 U11.123@535.69,668.9
  Bottom Layer w5: CN11.45@-300,-400 -348.46,-351.54 -348.46,533.54 -332.5,549.5 50.5,549.5 CN9.2@100,500
PD8: CN10.14 CN12.10 U11.77 | length 2978.8
  Top Layer w5: U11.77@1219.75,1018.31 1220,1018.56 1220,1240 v1(1243,1263)
  Signal w5: v1(1243,1263) 1607,1263 1760.9,1416.9 1970.76,1416.9 2032.66,1355 2156,1355 CN12.10@2200,1399
  Bottom Layer w5: CN10.14@1900,100 1944.1,144.1 2225.03,144.1 2287,206.07 2287,1310.44 2200,1397.44 CN12.10@2200,1399
PD9: CN10.16 CN11.69 U11.78 | length 5643.9
  Top Layer w5: v1(1186,1078) 1200.06,1063.94 U11.78@1200.06,1018.31 ; v1(1242,-1144) 1545,-1144 1689,-1000 1689,-3 1739,47 1853,47 CN10.16@1900,0 2021,121 2021,957 1966,1012 1727,1012 1683.5,1055.5 v1(1683.5,1086.5)
  Signal w5: CN11.69@-300,-1600 -253,-1553 -253,-1273 -229,-1249 1137,-1249 v1(1242,-1144) ; v1(1186,1078) 1208,1100 1670,1100 v1(1683.5,1086.5)
PD10: CN12.65 U11.79 | length 3263.2
  Top Layer w5: v1(1180,663) 1181,664 1181,1017.69 U11.79@1180.38,1018.31
  Signal w5: v1(1180,663) 1208,635 1480,635 1501,614 1501,-1319 1583,-1401 CN12.65@2100,-1401
PD11: CN12.45 U11.80 | length 2278.2
  Top Layer w5: v1(1160,795) 1161,796 1161,1018 U11.80@1160.69,1018.31
  Signal w5: v1(1160,795) 1161,796 1725.79,796 1749.79,772 1982.28,772 2006,748.28 2006,536.43 2014,528.43 2014,-315 CN12.45@2100,-401
PD12: CN12.43 U11.81 | length 2188.8
  Top Layer w5: v1@1141,838.02 v1(1141,842) ; v1@1141.01,838.01 U11.81@1141.01,1018.31
  Signal w5: v1(1141,842) 1502.79,842 1533.79,811 1732,811 1756,787 1988.5,787 2021,754.5 2021,542.64 2029,534.64 2029,-230 CN12.43@2100,-301
PD13: CN12.41 U11.82 | length 2106.5
  Top Layer w5: v1(1121,865) 1121,1017.98 U11.82@1121.32,1018.31
  Signal w5: v1(1121,865) 1501,865 1540,826 1741.79,826 1765.79,802 2006,802 2036.8,771.2 2036.8,548.05 2047,537.85 2047,-148 CN12.41@2100,-201
PD14: CN7.16 CN12.46 U11.85 | length 3064.1
  Top Layer w5: v1(1061.5,1066.29) 1062.27,1065.52 U11.85@1062.27,1018.31 ; CN7.16@1900,1060 2011.07,1060 2037.07,1034 2037.07,37.07 1951,-49 1873,-49 1849,-73 1849,-330 1869,-350 2149,-350 CN12.46@2200,-401
  Signal w5: v1(1061.5,1066.29) 1126.22,1131 1633,1131 1707,1205 1830.03,1205 1850,1185.03 1850,1110 CN7.16@1900,1060
PD15: CN7.18 CN12.48 U11.86 | length 2667.5
  Top Layer w5: U11.86@1042.58,1018.31 1042.58,967.42 1064,946 v2(1098.94,946) ; CN7.18@1900,960 1976,960 1986,950 v1(1986,740) v1@1989,737
  Signal w5: v2(1098.94,946) 1119.24,946 1175.27,1002.03 1857.97,1002.03 CN7.18@1900,960 CN7.18@1902.5,957.5 ; v1(1986,740) 1952,706 1952,569.21 1999,522.21 1999,-348.23 2044,-393.23 2044,-420 2070.41,-446.41 2142.97,-446.41 2197.56,-501 CN12.48@2200,-501
PE0: CN10.33 CN12.64 SB187.2 SB190.1 | length 3947.6
  Top Layer w5: v1@585.8,-1168.8 821.4,-1404.4 1676.6,-1404.4 1738,-1343 1738,-962 CN10.33@1800,-900 1850,-950 2129,-950 2150,-971 2150,-1251 CN12.64@2200,-1301
  Bottom Layer w5: v1(585.3,-1169.3) 584,-1168 584,79.5 614.5,79.5 622,87 622,231.44 615.44,238 SB187.2@586,238
PE1: CN11.61 SB14.1 SB189.1 | length 2170.5
  Top Layer w5: CN11.61@-300,-1200 -251,-1151 329,-1151 v1(475,-1005) ; SB14.1@297,-247.75 297,-274 311,-288 v1(475,-288)
  Bottom Layer w5: v1(475,-1005) v1(475,-288) 525,-238 SB189.1@525,79
PE2: CN9.14 CN11.46 U11.1 | length 1555.5
  Top Layer w5: CN11.46@-200,-400 -55,-255 21,-255 51,-225 51,-149 CN9.14@100,-100 100,-102.02 161,-163.02 161,-231 254,-324 503.14,-324 581,-246.14 581,106.07 609.51,134.58 U11.1@609.51,181.69
PE3: CN9.22 CN11.47 U11.2 | length 1578.6
  Top Layer w5: CN11.47@-300,-500 -257,-457 -229.55,-457 ; -229.53,-457.03 -170.47,-457.03 ; -170.45,-457 -29.55,-457 ; -29.53,-457.03 29.53,-457.03 ; 29.55,-457 57,-457 CN9.22@100,-500 ; v1(253,-344) 504.36,-344 596,-252.36 596,99.85 629.2,133.05 U11.2@629.2,181.69
  Signal w5: CN9.22@80.34,-500 CN9.22@100,-500
  Bottom Layer w5: CN9.22@100,-501.9 CN9.22@100,-500 225,-500 253,-472 v1(253,-344)
PE4: CN9.16 CN11.48 U11.3 | length 1589.5
  Top Layer w5: CN9.16@100,-200 184,-284 184,-327 221,-364 505.57,-364 611,-258.57 611,93.64 648.88,131.52 U11.3@648.88,181.69
  Bottom Layer w5: CN11.48@-200,-500 -146,-446 -146,-341.03 -47,-242.03 57.97,-242.03 CN9.16@100,-200
PE5: CN9.18 CN11.50 U11.4 | length 1584.5
  Top Layer w5: CN9.18@100,-300 182,-382 508.78,-382 626,-264.78 626,87.43 668.57,129.99 U11.4@668.57,181.69
  Bottom Layer w5: CN11.50@-200,-600 -198.44,-600 -116,-517.56 -116,-368.03 -90,-342.03 54.87,-342.03 96.9,-300 CN9.18@100,-300
PE6: CN9.20 CN11.62 U11.5 | length 2063.6
  Top Layer w5: CN9.20@100,-400 512,-400 641,-271 641,81.21 688.25,128.47 U11.5@688.25,181.69
  Bottom Layer w5: CN11.62@-200,-1200 -92,-1092 -92,-468.03 -66.94,-442.97 57.03,-442.97 CN9.20@100,-400
PE7: CN10.20 CN12.44 U11.58 | length 1634.2
  Top Layer w5: U11.58@1372.31,668.9 1372.31,669 1415,669 1419,673 1626,673 1752,547 v1(1752,528) ; CN10.20@1900,-200 1950,-250 2149,-250 CN12.44@2200,-301
  Signal w5: v1(1752,528) 1752,-138 1764,-150 1850,-150 CN10.20@1900,-200
PE8: CN10.18 CN12.40 U11.59 | length 1537.5
  Top Layer w5: U11.59@1372.31,688.58 1631.63,688.58 1776.21,544 v1(1850,544) ; CN10.18@1900,-100 1943.03,-143.03 2157.97,-143.03 CN12.40@2200,-101
  Signal w5: v1(1850,544) 1850,-50 CN10.18@1900,-100
PE9: CN10.4 CN12.52 U11.60 | length 2051.7
  Top Layer w5: U11.60@1372.31,708.27 1633.16,708.27 1699.43,642 1776.66,642 ; 1776.69,642.03 1857.97,642.03 CN10.4@1900,600
  Signal w5: CN10.4@1900,600 1984,516 1984,-354.44 2028,-398.44 2028,-621 2058,-651 2150,-651 CN12.52@2200,-701
PE10: CN10.24 CN12.47 U11.63 | length 1881
  Top Layer w5: U11.63@1372.31,767.32 1420.32,767.32 1441,788 1554.75,788 v1(1568.75,774) ; CN10.24@1900,-400 1999,-400 CN12.47@2100,-501
  Signal w5: v1(1568.75,774) 1669,774 1712,731 1712,190.35 1720,182.35 1720,-319.66 1758.32,-357.97 1857.97,-357.97 CN10.24@1900,-400
PE11: CN10.6 CN12.56 U11.64 | length 2374.4
  Top Layer w5: U11.64@1372.31,787.01 1414.01,787.01 1438,811 1568,811 1721.97,657.03 1908.31,657.03 1947.93,617.41 1947.93,614.07 1948,614 1948,548 CN10.6@1900,500
  Signal w5: CN10.6@1900,500 1969,431 1969,-361.23 1969.57,-361.23 2013,-404.66 2013,-792 2067.97,-846.97 2145.97,-846.97 CN12.56@2200,-901
PE12: CN12.49 SB168.1 SB169.2 U11.65 | length 2650
  Top Layer w5: v1(1298,767) 1298,783.8 1320.9,806.69 U11.65@1372.31,806.69
  Signal w5: v1@1299,768 1525.21,768 1580.33,712.89 1583.86,712.89 1629.82,758.85 1633.36,758.85 1647.5,744.71 1647.5,741.17 1601.54,695.21 1601.54,691.67 1615.68,677.53 1619.22,677.53 1665.18,723.49 1668.72,723.49 1682.86,709.35 1682.86,705.81 1636.9,659.85 1636.9,656.32 1651.04,642.18 1654.57,642.18 1679.32,666.92 1682.86,666.92 1697,652.78 1697,649.25 1672.25,624.5 1672.25,620.96 1697,596.21 1697,184.14 1704,177.14 1704,-341 v1(1714,-351)
  Bottom Layer w5: SB169.2@1630.25,-459 SB168.1@1630.25,-400 1630.25,-361.78 1640.6,-351.43 1971.43,-351.43 2007,-387 2007,-573 2035,-601 CN12.49@2100,-601
PE13: CN10.10 CN12.55 U11.66 | length 2359.4
  Top Layer w5: U11.66@1372.31,826.38 1372.31,826 1574.21,826 1651.21,749 1925,749 1963,711 1963,363 CN10.10@1900,300
  Signal w5: CN10.10@1900,300 1954,246 1954,-367.45 1984,-397.45 1984,-784.21 2042.39,-842.61 ; 2042,-843 CN12.55@2100,-901
PE14: CN12.51 SB170.1 SB177.2 U11.67 | length 2462.2
  Top Layer w5: v1(1290.53,741) 1278,753.53 1278,808.05 1316.02,846.06 U11.67@1372.31,846.06 ; v1(1737,-617) 1767.47,-647.47 1986.47,-647.47 2040,-701 CN12.51@2100,-701
  Signal w5: v1(1290.53,741) 1303.89,727.64 1544.36,727.64 1682,590 1682,177.92 1689,170.92 1689,-569 v1(1737,-617)
  Bottom Layer w5: SB170.1@1630.25,-518 SB177.2@1630.25,-577 1630.25,-604.25 1643,-617 v1(1737,-617)
PE15: CN12.53 SB157.1 SB180.2 U11.68 | length 2530.1
  Top Layer w5: v1(1282,710) 1263,729 1263,817.75 1311,865.75 U11.68@1372.31,865.75
  Signal w5: v1(1282,710) 1519,710 1552,677 1552,475.56 1598,429.56 v1(1598,-199) v1(1598,-677)
  Bottom Layer w5: v1(1598,-677) SB180.2@1630.5,-677 1630.5,-652.5 1640.03,-642.97 1941.97,-642.97 CN12.53@2100,-801 ; v1(1598,-199) 1629.25,-199 SB157.1@1630.25,-200
PF0: CN9.21 CN11.53 U11.10 | length 2025.5
  Top Layer w5: CN9.21@0,-500 52,-552 648,-552 853,-347 853,66.01 786.68,132.33 U11.10@786.68,181.69
  Signal w5: CN11.53@-300,-800 -248,-748 -167,-748 -145,-726 -145,-579.9 -65.1,-500 CN9.21@0,-500
PF1: CN9.19 CN11.51 U11.11 | length 2068.7
  Top Layer w5: U11.11@806.36,181.69 806.36,133.86 868,72.22 868,-379 v1(849,-398)
  Signal w5: CN11.51@-300,-700 -347.93,-652.07 -347.93,-575.1 -320.52,-547.69 -147.69,-547.69 CN9.19@0,-400 49,-449 798,-449 v1(849,-398)
PF2: CN9.17 CN11.52 U11.12 | length 2427.8
  Top Layer w5: CN11.52@-200,-700 -142.03,-642.03 675.32,-642.03 883,-434.34 883,78.44 826.05,135.39 U11.12@826.05,181.69
  Bottom Layer w5: CN11.52@-200,-700 -249,-651 -249,-578.38 -218.31,-547.69 -168.9,-547.69 -131,-509.79 -131,-358 -73,-300 CN9.17@0,-300
PF3: CN8.14 CN12.58 U11.13 | length 4001.6
  Top Layer w5: v1(881.1,-489) 898,-472.1 898,84.65 845.73,136.92 U11.13@845.73,181.69 845.73,360.45 949,463.72 v1(949,464)
  Signal w5: CN8.14@100,800 108,800 139,769 773.43,769 948.98,593.45 948.98,464.02 v1@949,462
  Bottom Layer w5: v1(881.1,-489) 795,-575.1 795,-718 1175,-1098 1654,-1098 1804,-948 2147,-948 CN12.58@2200,-1001
PF4: CN12.38 U11.14 | length 1868.2
  Top Layer w5: U11.14@865.42,181.69 865.42,146.58 v1(883,129)
  Bottom Layer w5: v1(883,129) 954,129 1006,181 1476.25,181 1532,125.25 1532,-79 1611,-158 1776.66,-158 ; 1776.69,-157.97 1823.31,-157.97 ; 1823.34,-158 1876.66,-158 ; 1876.69,-157.97 1923.31,-157.97 1923.37,-158.03 2221.97,-158.03 2247.93,-132.07 2247.93,-48.93 CN12.38@2200,-1
PF5: CN8.16 CN12.36 U11.15 | length 3153
  Top Layer w5: U11.15@885.1,181.69 v1(885.1,229.39) 885.1,347.1 974,436 974,477.64 962.54,489.1 v1(892.8,489.1)
  Signal w5: CN8.16@100,700 249.9,700 270.9,679 821,679 879,621 879,503.73 892.8,489.93 v1(892.8,489.1)
  Bottom Layer w5: v1(885.1,229.39) 905.39,209.1 995.83,209.1 996.03,208.9 1493.76,208.9 1561.8,140.86 1561.8,-55.14 1649.63,-142.97 1929.53,-142.97 1929.58,-143.03 2129.97,-143.03 2148.62,-124.38 2148.62,47.62 CN12.36@2200,99
PF6: CN11.9 U11.18 | length 4279.5
  Top Layer w5: CN11.9@-300,1400 -251,1351 -251,1271 -273,1249 -328,1249 -354.5,1222.5 -354.5,-710.84 -323.31,-742.03 -276.69,-742.03 ; -276.66,-742 -223.34,-742 ; -223.31,-742.03 -132.03,-742.03 -47.03,-657.03 668.96,-657.03 669.03,-657.1 751.9,-657.1 913,-496 913,69.24 944.47,100.72 944.47,181.38 U11.18@944.16,181.69
PF7: CN9.26 CN11.11 U11.19 | length 4168.3
  Top Layer w5: CN11.11@-300,1300 -369.5,1230.5 -369.5,-717.05 -329.53,-757.03 -270.47,-757.03 ; -270.45,-757 -229.55,-757 ; -229.53,-757.03 42.97,-757.03 CN9.26@100,-700 737.25,-700 928,-509.25 928,63.03 963.84,98.87 U11.19@963.84,181.69
PF8: CN9.24 CN11.54 U11.20 | length 2023.3
  Top Layer w5: v1(873.1,-600.9) 943,-531 943,56.82 983.53,97.34 U11.20@983.53,181.69
  Signal w5: CN11.54@-200,-800 -158,-800 -123.55,-765.55 -123.55,-700.55 -73,-650 50,-650 CN9.24@100,-600 100,-600.9 v1(873.1,-600.9)
PF9: CN9.28 CN11.56 U11.21 | length 2134.2
  Top Layer w5: CN11.56@-200,-900 -157.03,-857.03 23.31,-857.03 75.48,-804.86 95.14,-804.86 CN9.28@100,-800 846,-800 958,-688 958,50.6 1001.5,94.1 1001.5,179.98 U11.21@1003.21,181.69
PF10: CN12.42 U11.22 | length 1764.5
  Top Layer w5: v2@1022.9,134 U11.22@1022.9,181.69
  Bottom Layer w5: v2(1022,135) 1048,161 1109,161 1125,145 1125,-305.21 1158.79,-339 1467,-339 1554,-252 2149,-252 CN12.42@2200,-201 ; v2@1022.9,134 v2@1022.95,134.05
PF11: CN12.62 U11.49 | length 2411.2
  Top Layer w5: U11.49@1372.31,491.73 1372.57,492 v1(1573,492)
  Signal w5: v1(1573,492) 1622,443 1622,174.28 1644,152.28 1644,-1084.9 1718.1,-1159 2076.66,-1159 ; 2076.69,-1158.97 2123.31,-1158.97 ; 2123.34,-1159 2158,-1159 CN12.62@2200,-1201
PF12: CN7.20 CN12.59 U11.50 | length 3263.3
  Top Layer w5: v1(1299.28,615) 1298.5,614.22 1298.5,531.5 1318.58,511.42 U11.50@1372.31,511.42
  Signal w5: CN7.20@1900,860 1900,855.1 2123.9,855.1 2152.07,826.93 2152.07,-334.07 2168,-350 2234,-350 2259,-375 2259,-1026 2230,-1055 2146,-1055 CN12.59@2100,-1101
  Bottom Layer w5: v1(1299.28,615) 1406.28,722 1600,722 1692,814 1855,814 1855,815 CN7.20@1900,860
PF13: CN10.2 CN12.57 U11.53 | length 2573.1
  Top Layer w5: U11.53@1372.31,570.47 1423.9,570.47 1436.61,583.19 1574.97,583.19 1710.16,448 v1(1732,448)
  Signal w5: CN10.2@1900,700 1857.97,742.03 1754.03,742.03 1732,720 v1(1732,448) 1735,445 1735,-313.44 1763.58,-342.03 1907.37,-342.03 1969,-403.66 1969,-861.03 2100,-992.03 CN12.57@2100,-1001
PF14: CN10.8 CN12.50 U11.54 | length 1944.9
  Top Layer w5: U11.54@1372.31,590.16 1420.36,590.16 1428.39,598.19 1588.76,598.19 1713.94,473 1751.36,473 1777.36,447 1853,447 CN10.8@1900,400 ; CN12.50@2200,-601 2252,-549 2252,327 v1(2229,350)
  Bottom Layer w5: CN10.8@1900,400 1977,400 2027,350 v1(2229,350)
PF15: CN10.12 CN12.60 U11.55 | length 2756.4
  Top Layer w5: U11.55@1372.31,609.84 1418.83,609.84 1422.18,613.19 1606.81,613.19 v1(1662,558) ; CN12.60@2200,-1101 CN12.60@2202.44,-1101
  Signal w5: v1(1662,558) v1(1662,252) 1662,176.71 1674,164.71 1674,-593 1728,-647 1925,-647 1954,-676 1954,-1107 1991,-1144 2070.45,-1144 ; 2070.47,-1143.97 2129.53,-1143.97 ; 2129.55,-1144 2157,-1144 CN12.60@2200,-1101
  Bottom Layer w5: v1(1662,252) 1848,252 CN10.12@1900,200
PG0: CN9.29 CN11.59 U11.56 | length 3950.6
  Top Layer w5: CN11.59@-300,-1100 -248,-1048 -248,-981 -221,-954 -185.07,-954 -131.07,-900 CN9.29@0,-900 46,-946 1641,-946 v1(1666,-921) ; U11.56@1373.44,628.4 1558.4,628.4 v1(1583,653) v1@1583,658
  Signal w5: v1(1583,653) 1642,594 1642,175.5 1659,158.5 1659,-602 1666,-609 v1(1666,-921)
PG1: CN9.30 CN11.58 U11.57 | length 3601.7
  Top Layer w5: CN9.30@100,-900 1529,-900 v1(1568,-861) ; U11.57@1372.31,649.21 v1@1532,649.21
  Signal w5: CN11.58@-200,-1000 -199,-1000 -50,-851 51,-851 CN9.30@100,-900 CN9.30@112,-888 ; v1(1532,649) 1532,471 1578,425 1578,-685.28 1609,-716.28 1609,-820 v1(1568,-861)
PG2: CN11.42 U11.87 | length 2396.8
  Top Layer w5: CN11.42@-200,-200 -197.01,-200 -100,-102.99 -100,707 -57,750 137.52,750 v1(179.62,792.1) ; v1(913,889) 931,871 1011.79,871 1022.9,882.11 U11.87@1022.9,1018.31
  Bottom Layer w5: v1@180.9,792.1 v1(179.62,792.1) 181,793.48 181,815 359,993 752,993 856,889 v1(913,889)
PG3: CN11.44 U11.88 | length 2370.1
  Top Layer w5: v1(1003.21,1065.78) U11.88@1003.21,1018.31 U11.88@1004,1019.09
  Bottom Layer w5: CN11.44@-200,-300 -198.44,-300 -77.9,-179.46 -77.9,87.44 -23.31,142.03 133.58,142.03 171,179.44 171,725 152,744 152,810 354,1012 949.43,1012 v1(1003.21,1065.78)
PG4: CN12.69 U11.89 | length 3490.8
  Top Layer w5: U11.89@983.53,1018.31 983.53,975.47 v1(992,967)
  Signal w5: v1(992,967) 1017,942 1017,652.56 1098.56,571 1367,571 1471,467 1471,-1401.79 1670.21,-1601 CN12.69@2100,-1601
PG5: CN12.68 JP4.2 U11.90 | length 4985.9
  Top Layer w5: v1(963.84,1065.16) U11.90@963.84,1018.31 U11.90@964.16,1017.99
  Signal w5: v1(963.84,1065.16) 1032,997 1032,658.77 1104.77,586 1443,586 1486,543 1486,-1395.57 1641.43,-1551 v1(1666,-1551)
  Bottom Layer w5: JP4.2@700,1650 700,1454 691,1445 691,1294.35 611.65,1215 505,1215 476,1186 476,1057 506,1027 925.69,1027 v1(963.84,1065.16) ; v1(1666,-1551) 2150,-1551 CN12.68@2200,-1501
PG6: CN12.70 SB200.1 SB201.1 U11.91 | length 4787.5
  Top Layer w5: v1(944.16,966.16) U11.91@944.16,1018.31
  Signal w5: v1(944.16,966.16) 893,915 893,718.43 1085.43,526 1387,526 1456,457 1456,-1408 1699,-1651 2150,-1651 CN12.70@2200,-1601
  Bottom Layer w5: SB201.1@1379,-1690.25 SB200.1@1320,-1690.25 1320,-1623.53 1348.53,-1595 1481,-1595 1541,-1655 2146,-1655 CN12.70@2200,-1601
PG7: SB131.1 SB195.1 U11.92 | length 3511.3
  Top Layer w5: U11.92@924.47,1018.31 v1(924.47,1066.29)
  Signal w5: v1(924.47,1066.29) 863,1004.81 863,706 1076,493 1356,493 1399,450 1399,234 1426,207 1426,-1476 v1(1452,-1502)
  Bottom Layer w5: v1(924.47,1066.29) 953,1094.81 SB131.1@953,1119.25 ; v1(1452,-1502) 1808,-1502 ; 1809,-1501 1808,-1502 ; SB195.1@1847,-1501 1846,-1502 1808,-1502
PG8: SB130.1 SB193.2 U11.93 | length 3548.6
  Top Layer w5: v1(904.79,966.82) U11.93@904.79,1018.31 904.47,1018.62 904.47,1088.47 935.25,1119.25 v1(1050,1119.25)
  Signal w5: v1(904.79,966.82) 878,940.03 878,712.21 1079.21,511 1380.79,511 1441,450.79 1441,-1433 v1(1450,-1442)
  Bottom Layer w5: SB130.1@1012,1119.25 v1(1050,1119.25) ; v1(1450,-1442) SB193.2@1847,-1442
PG9: CN11.63 U11.124 | length 2861
  Top Layer w5: v1(229,-117) 171,-59 171,572 243.53,644.53 490,644.53 494.59,649.11 535.69,649.11 U11.124@535.69,649.21
  Bottom Layer w5: CN11.63@-300,-1300 -257,-1257 247,-1257 294,-1210 294,-182 v1(229,-117)
PG10: CN13.2 SB10.1 SB118.1 SB192.2 U11.125 | length 4738.1
  Top Layer w5: v1(98,-1399) 273,-1399 309,-1363 v1(309,-1229) ; v1@275,-114 v1(275,-112) 186,-23 186,565.79 249.74,629.53 U11.125@535.69,629.53 571.24,629.53 616,674.28 616,748 585,779 585,951.24 567.24,969 479.02,969 441,1007.02 v1(441,1120) ; v1(654,1584.13) 664,1574.13 SB10.1@664,1551.75
  Signal w5: v1(98,-1399) 73,-1424 73,-1773 CN13.2@300,-2000
  Bottom Layer w5: SB192.2@62.5,-1399 v1(98,-1399) ; v1(275,-112) 309,-146 v1(309,-1229) ; v1(441,1120) 441,1205 466,1230 605.43,1230 677,1301.57 677,1448 685,1456 685,1581.06 681.93,1584.13 v1(654,1584.13) SB118.1@654,1552
PG11: CN13.4 SB16.2 SB196.2 U11.126 | length 3468.1
  Top Layer w5: v1(359.53,-107) 304,-107 201,-4 201,557 253.84,609.84 U11.126@535.69,609.84 ; CN13.4@400,-2000 SB16.2@400,-1887.75
  Signal w5: v1(140,-1599) 140,-1740 CN13.4@400,-2000
  Bottom Layer w5: SB196.2@62.5,-1599 v1(140,-1599) 256,-1599 359.53,-1495.47 v1(359.53,-107)
PG12: CN13.8 SB18.2 SB191.1 U11.127 | length 3414.8
  Top Layer w5: v1(316.53,-81) 216,19.53 216,542.3 263.86,590.16 U11.127@535.69,590.16 ; CN13.8@600,-2000 SB18.2@600,-1887.75
  Signal w5: v1(284,-1339) 284,-1694.63 393.37,-1804 404,-1804 CN13.8@600,-2000
  Bottom Layer w5: SB191.1@62.5,-1339 v1(284,-1339) 325,-1298 325,-89.47 v1(316.53,-81)
PG13: CN13.6 SB17.2 SB194.2 U11.128 | length 3366.6
  Top Layer w5: v1(342.94,-69.94) 231,42 231,530 271.47,570.47 U11.128@535.69,570.47 ; CN13.6@500,-2000 SB17.2@500,-1887.75
  Signal w5: v1@218,-1497 v1(220,-1499) 220,-1720 CN13.6@500,-2000
  Bottom Layer w5: SB194.2@62.5,-1499 270,-1499 339.53,-1429.47 339.53,-73.36 v1(342.94,-69.94)
PG14: CN12.61 U11.129 | length 3470.9
  Top Layer w5: U11.129@535.69,550.79 579.79,550.79 594,565 594,587.53 689.47,683 1079.9,683 v1(1107.9,711)
  Signal w5: v1(1107.9,711) 1201,711 1252,660 1485,660 1516,629 1516,-1137 1580.4,-1201.4 2100,-1201.4 CN12.61@2100,-1201
PG15: CN11.64 SB160.2 | length 2705.7
  Top Layer w5: CN11.64@-200,-1300 -87,-1187 378.47,-1187 v1(453,-1112.47)
  Bottom Layer w5: SB160.2@290.53,652.5 252.5,652.5 235,635 235,204 281,158 350.79,158 493,15.79 493,-241.72 452,-282.72 v1@452,-1112.47
PH0: SB12.2 SB147.1 SB148.1 U11.23 | length 296.9
  Top Layer w5: SB12.2@1022.99,66.5 1039.5,83 1039.5,122.49 1043.4,126.39 1043.4,180.88 U11.23@1042.58,181.69 1045.86,184.97 1045.86,231.86 v2(1046,232)
  Bottom Layer w5: SB147.1@1013.7,271.25 SB148.1@1072.7,271.25 1072.7,243.86 1060.84,232 v2(1046,232) 1043.42,232 v2@1043,232.42
PH1: SB13.2 SB156.1 U11.24 | length 195.8
  Top Layer w5: U11.24@1061.45,180.88 1061.45,115.45 1083,93.91 SB13.2@1083,69.75 ; SB13.2@1080.99,67.74 SB13.2@1081.99,66.75
  Bottom Layer w5: SB156.1@1024,69.75 1024,103.96 1034.04,114 v2(1060,114)
PH3-BOOT0: CN11.7 R38.1 SB171.2 SB183.2 | length 2114.5
  Top Layer w5: CN11.7@-300,1500 -252,1452 -169,1452 -152,1435 -152,284 v1(-125,257) ; v1@250.9,417 v1(256,417) R38.1@371.5,417
  Signal w5: v1(-125,257) -124.9,256.9 70.35,256.9 70.47,257.03 229.93,257.03 249.9,277 v1(255,277)
  Bottom Layer w5: v1@250.9,417 v1(256,417) SB171.2@291,417 ; v1@255,410.9 v1(255,277) 255,251 268,238 SB183.2@291,238
STLINK_USB_DM: CN1.2 U1.1 U1.6 U2.32 | length 788.8
  Top Layer w6.1: U2.32@1117.32,2479.53 1140.73,2479.53 1143.07,2481.87 1443.08,2481.87 1520.5,2559.29 1520.5,2611.95 1550.4,2641.85 U1.6@1550.4,2666.76 U1.1@1550.4,2761.24 1550.4,2786.85 1520.5,2816.75 1520.5,2849.76 1525.59,2854.85 CN1.2@1525.59,2885
STLINK_USB_DP: CN1.3 R9.1 U1.3 U1.4 U2.33 | length 828.8
  Top Layer w6.1: U2.33@1117.32,2499.21 1140.73,2499.21 1143.07,2496.87 1436.87,2496.87 1505.5,2565.5 1505.5,2611.95 1475.6,2641.85 U1.4@1475.6,2666.76 ; R9.1@1411,2666.5 1475.35,2666.5 U1.4@1475.6,2666.76 ; CN1.3@1500,2885 1500,2854.85 1505.5,2849.35 1505.5,2816.75 1475.6,2786.85 U1.3@1475.6,2761.24 U1.4@1475.6,2666.76
STM_JTCK: SB103.2 U2.37 | length 1526.7
  Top Layer w5: v2(496,2799) 496,2869 614,2987 1242,2987 1290,2939 1290,2647 1246,2603 1060,2603 1058.27,2604.73 U2.37@1058.27,2617.32
  Bottom Layer w5: SB103.2@457.75,2800 495,2800 v2(496,2799)
STM_JTMS: SB107.2 U2.34 | length 876.6
  Top Layer w5: v1(976,2518) 1116.43,2518 U2.34@1117.32,2518.9
  Bottom Layer w5: SB107.2@457.75,2600 716,2600 798,2518 ; v1(976,2518) 798,2518 ; v1@979.6,2517.6 975.6,2517.6 974.5,2516.5 799.5,2516.5 798,2518
STM_RST: C2.2 JP2.2 R5.1 U2.7 | length 2236.5
  Top Layer w5: U2.7@782.68,2440.1 810.42,2440.1 861.42,2491.1 861.42,2534 v1(812,2583.42) ; v2(812,2643) 826.11,2643 842,2658.89 R5.1@842,2684.5 C2.2@901,2684.5
  Signal w5: JP2.2@-300,2300 -300,2613 52,2965 727.19,2965 812,2880.19 v2(812,2643) v1(812,2583.42)
SWO_MCU: SB108.1 SB141.1 U14.6 | length 2364.4
  Bottom Layer w5: SB141.1@409,770.75 525.65,770.75 568.31,813.41 568.31,902.31 601,935 763,935 832,866 985.57,866 1018.79,899.21 ; 1017,901 1017,1000 1054.83,1037.83 1189.17,1037.83 1206.37,1055.03 1206.37,1332.42 1081.9,1456.89 1081.9,1795.06 1136.84,1850 U14.6@1136.84,2150.98 1136.84,2180.5 1144.34,2188 1198,2188 SB108.1@1210,2176
T_JTCK: R14.2 SB100.1 U2.15 U2.26 | length 1874.1
  Top Layer w5: R14.2@81.5,2600 111.25,2600 142.25,2631 v2(142.25,2851) ; U2.15@881.1,2282.68 881.1,2365.1 899,2383 899,2384 ; v1(899,2555) 899,2384 ; U2.26@1117.32,2361.42 1117.32,2361.1 1072.07,2361.1 1071.75,2361.42 921.58,2361.42 899,2384
  Bottom Layer w5: SB100.1@142.25,2900 v2(142.25,2851) 850,2851 878,2823 878,2626 ; 879,2626 899,2606 v1(899,2555)
T_JTDI: U2.17
T_JTDO: U2.16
